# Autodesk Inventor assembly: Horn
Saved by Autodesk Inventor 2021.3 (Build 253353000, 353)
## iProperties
Created: 2022-04
Part Number: Horn
Document SubType Name: Assembly
Designer: Administrator
Title: Horn v2
Author: Administrator
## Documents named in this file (2)
- c:\worker\convert-fusion-r02\tmp\job-1\360\output\files\c51cb509-9746-4710-8d38-e36b0d1018b1\48b62c77-1544-417f-bb2d-42cdfa0d16eb.iam
- c:\worker\convert-fusion-r02\tmp\job-1\360\output\files\c51cb509-9746-4710-8d38-e36b0d1018b1\Component1.ipt
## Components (1 placed, 1 different names)
1. Component1:1
